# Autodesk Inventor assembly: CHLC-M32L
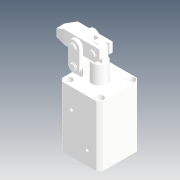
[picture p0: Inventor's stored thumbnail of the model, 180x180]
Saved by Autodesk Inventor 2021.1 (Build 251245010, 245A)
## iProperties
Company: Microsoft
Created: 2019-11
Part Number: CHLC-M32L
Description: STEP AP214
Document SubType Name: Assembly
Designer: user
Title: CHLC-M32L.STEP
Author: Windows
Revision Number: ÈÎºÎ
Sending System: SolidWorks 2015
Preprocessor: SwSTEP 2.0
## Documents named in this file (10)
- D:\Vault_2016\Projekty\Clamptek\Hydraulic\CHLC\CHLC-32\Inventor\CHLC-M32L\CHLC-M32L.iam
- D:\Vault_2016\Projekty\Clamptek\Hydraulic\CHLC\CHLC-32\Inventor\CHLC-M32L\CHLC-M32-±¾Ìå.ipt
- D:\Vault_2016\Projekty\Clamptek\Hydraulic\CHLC\CHLC-32\Inventor\CHLC-M32L\CHLC-M32-͹̨.ipt
- D:\Vault_2016\Projekty\Clamptek\Hydraulic\CHLC\CHLC-32\Inventor\CHLC-M32L\CHLC-32-02_1.ipt
- D:\Vault_2016\Projekty\Clamptek\Hydraulic\CHLC\CHLC-32\Inventor\CHLC-M32L\CHLC-32-03_1.ipt
- D:\Vault_2016\Projekty\Clamptek\Hydraulic\CHLC\CHLC-32\Inventor\CHLC-M32L\CHLC-32-04_1.ipt
- D:\Vault_2016\Projekty\Clamptek\Hydraulic\CHLC\CHLC-32\Inventor\CHLC-M32L\CHLC-32-08_1.ipt
- D:\Vault_2016\Projekty\Clamptek\Hydraulic\CHLC\CHLC-32\Inventor\CHLC-M32L\LHC01D-32-01_1.ipt
- D:\Vault_2016\Projekty\Clamptek\Hydraulic\CHLC\CHLC-32\Inventor\CHLC-M32L\M6LS.ipt
- D:\Vault_2016\Projekty\Clamptek\Hydraulic\CHLC\CHLC-32\Inventor\CHLC-M32L\Ñ¹±Û.ipt
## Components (17 placed, 17 different names)
1. CHLC-M32-±¾Ìå_1
2. CHLC-M32-͹̨_2
3. CHLC-32-02_1_3
4. CHLC-32-03_1_4
5. CHLC-32-04_1_5
6. CHLC-32-08_1_6
7. LHC01D-32-01_1_7
8. CHLC-32-03_1_8
9. CHLC-32-04_1_9
10. LHC01D-32-01_1_10
11. LHC01D-32-01_1_11
12. LHC01D-32-01_1_12
13. LHC01D-32-01_1_13
14. LHC01D-32-01_1_14
15. M6LS_15
16. M6LS_16
17. Ñ¹±Û_17
